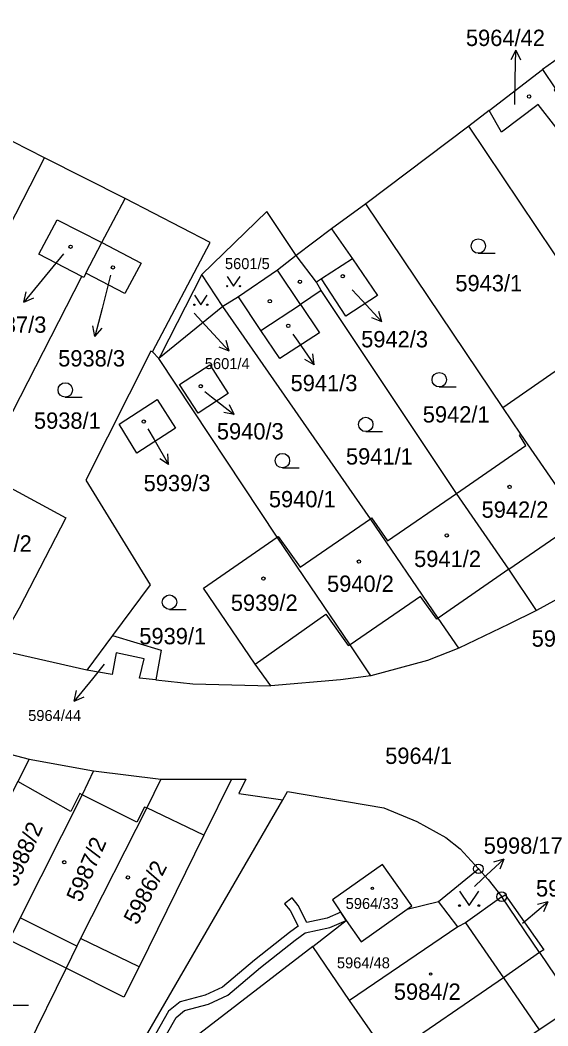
# Model space of a CAD drawing. Extents: x -644096 to -634268, y -1141430 to -1133463.
# Drawn here: x -639627.9 to -639573, y -1138928.4 to -1138823.8 of the extents above; entities that cross this region are included whole.
import ezdxf

# ---------------------------------------------------------------- set-up
doc = ezdxf.new("R2010")
doc.units = 0
for name, color, linetype in [('_CIVIL_CONSTRUCTION', 7, 'Continuous'), ('B_Hranice _3D', 7, 'Continuous'), ('M_Svah_Nasyp', 7, 'Continuous'), ('M_Svah_Zarez', 7, 'Continuous'), ('svrsek_osa_sjezdy', 7, 'Continuous'), ('svrsek_osa_terminal_VRT', 7, 'Continuous'), ('svrsek_osa_VRT', 7, 'Continuous'), ('svrsek_popisy_VRT', 7, 'Continuous'), ('terminal_VRT', 7, 'Continuous')]:
    doc.layers.add(name, color=color, linetype=linetype)

msp = doc.modelspace()

# ---------------------------------------------------------------- linework, layer by layer
at = {"layer": '_CIVIL_CONSTRUCTION'}
for centre, radius in [((-639580.24, -1138912.09), 0.5), ((-639580.24, -1138912.09), 0.0303), ((-639577.82, -1138914.99), 0.5), ((-639577.82, -1138914.99), 0.0303)]:
    msp.add_circle(centre, radius, dxfattribs=at)
at = {"layer": 'B_Hranice _3D'}
msp.add_lwpolyline([(-639615.83, -1138934.86), (-639611.7, -1138927.57), (-639610.82, -1138926.84), (-639608.33, -1138926.18), (-639606.31, -1138925.25), (-639602.91, -1138922.37), (-639599.29, -1138919.5), (-639598.25, -1138918.74), (-639595.69, -1138918.18), (-639593.99, -1138917.46), (-639594.56, -1138916.61), (-639595.99, -1138917.22), (-639598.08, -1138917.67), (-639599, -1138915.89), (-639599.63, -1138915.1), (-639600.41, -1138915.72), (-639599.84, -1138916.43), (-639599, -1138918.05), (-639599.89, -1138918.7), (-639603.55, -1138921.59), (-639606.85, -1138924.39), (-639608.67, -1138925.24), (-639611.28, -1138925.92), (-639612.48, -1138926.91), (-639616.67, -1138934.32)], dxfattribs=at)
at = {"layer": 'M_Svah_Nasyp'}
for p, q in [((-639593.35, -1138848.64), (-639596.58, -1138850.72)), ((-639598.76, -1138853.37), (-639601.15, -1138849.8)), ((-639602.87, -1138856.07), (-639598.76, -1138853.37)), ((-639577.07, -1138880.92), (-639569.66, -1138875.81)), ((-639577.07, -1138880.92), (-639584.44, -1138886.03)), ((-639586.25, -1138883.75), (-639593.6, -1138888.77)), ((-639584.57, -1138886.11), (-639586.25, -1138883.75)), ((-639603.47, -1138890.8), (-639596.13, -1138885.58)), ((-639596.13, -1138885.58), (-639593.8, -1138888.87)), ((-639584.44, -1138886.03), (-639584.57, -1138886.11)), ((-639593.8, -1138888.87), (-639593.6, -1138888.77)), ((-639622.65, -1138906.12), (-639628.16, -1138903.02)), ((-639621.71, -1138904.25), (-639622.65, -1138906.12)), ((-639621.45, -1138904.38), (-639621.71, -1138904.25)), ((-639615.79, -1138907.24), (-639621.45, -1138904.38)), ((-639614.99, -1138905.66), (-639615.79, -1138907.24)), ((-639614.73, -1138905.76), (-639614.99, -1138905.66)), ((-639608.8, -1138908.6), (-639614.73, -1138905.76)), ((-639622.01, -1138920.15), (-639627.9, -1138917.2)), ((-639581.59, -1138917.72), (-639577.64, -1138923.43)), ((-639615.55, -1138922.3), (-639621.65, -1138919.34)), ((-639577.64, -1138923.43), (-639573.92, -1138928.85))]:
    msp.add_line(p, q, dxfattribs=at)
at = {"layer": 'M_Svah_Zarez'}
for centre, radius in [((-639574.97, -1138831.74), 0.175), ((-639622.67, -1138847.37), 0.175), ((-639618.26, -1138849.52), 0.175), ((-639594.35, -1138850.44), 0.175), ((-639598.81, -1138851.01), 0.175), ((-639601.94, -1138853.04), 0.175), ((-639600.03, -1138855.6), 0.175), ((-639609.13, -1138861.88), 0.175), ((-639615.06, -1138865.56), 0.175), ((-639577, -1138872.36), 0.175), ((-639583.54, -1138877.4), 0.175), ((-639592.67, -1138880.13), 0.175), ((-639602.61, -1138881.9), 0.175), ((-639623.33, -1138911.4), 0.175), ((-639616.71, -1138912.98), 0.175), ((-639591.27, -1138914.13), 0.117), ((-639585.22, -1138923.04), 0.117)]:
    msp.add_circle(centre, radius, dxfattribs=at)
at = {"layer": 'svrsek_osa_sjezdy'}
for p, q in [((-639580.25, -1138848.05), (-639578.5, -1138848.05)), ((-639584.31, -1138861.96), (-639582.56, -1138861.96)), ((-639623.22, -1138863.02), (-639621.47, -1138863.02)), ((-639591.96, -1138866.61), (-639590.21, -1138866.61)), ((-639600.63, -1138870.37), (-639598.88, -1138870.37)), ((-639612.38, -1138885.1), (-639610.63, -1138885.1)), ((-639628.79, -1138926.27), (-639627.04, -1138926.27))]:
    msp.add_line(p, q, dxfattribs=at)
for points in [[(-639606.38, -1138850.46), (-639605.71, -1138851.47), (-639605.04, -1138850.46)], [(-639609.79, -1138852.4), (-639609.12, -1138853.41), (-639608.45, -1138852.4)], [(-639582.2, -1138914.42), (-639581.2, -1138915.92), (-639580.2, -1138914.42)]]:
    msp.add_lwpolyline(points, dxfattribs=at)
for centre, radius in [((-639580.25, -1138847.3), 0.75), ((-639606.38, -1138851.47), 0.067), ((-639605.04, -1138851.47), 0.067), ((-639609.79, -1138853.41), 0.067), ((-639608.45, -1138853.41), 0.067), ((-639584.31, -1138861.21), 0.75), ((-639623.22, -1138862.27), 0.75), ((-639591.96, -1138865.86), 0.75), ((-639600.63, -1138869.62), 0.75), ((-639612.38, -1138884.35), 0.75), ((-639582.2, -1138915.92), 0.1), ((-639580.2, -1138915.92), 0.1)]:
    msp.add_circle(centre, radius, dxfattribs=at)
at = {"layer": 'svrsek_osa_terminal_VRT'}
msp.add_arc((-642050.26, -1145189.6), 8802.25, 41.413152, 75.317049, dxfattribs=at)
at = {"layer": 'svrsek_popisy_VRT'}
for p, q in [((-639576.36, -1138826.92), (-639576.88, -1138827.91)), ((-639576.41, -1138829.92), (-639576.36, -1138826.92)), ((-639576.36, -1138826.92), (-639575.87, -1138827.93)), ((-639576.46, -1138832.57), (-639576.41, -1138829.92)), ((-639623.42, -1138848.12), (-639625.64, -1138850.82)), ((-639618.51, -1138850.32), (-639619.4, -1138853.79)), ((-639625.64, -1138850.82), (-639627.53, -1138853.15)), ((-639627.53, -1138853.15), (-639627.29, -1138852.06)), ((-639593.39, -1138851.85), (-639592.33, -1138852.98)), ((-639627.53, -1138853.15), (-639626.51, -1138852.69)), ((-639592.33, -1138852.98), (-639590.28, -1138855.18)), ((-639619.4, -1138853.79), (-639620.13, -1138856.7)), ((-639609.81, -1138854.29), (-639608.21, -1138856.02)), ((-639590.28, -1138855.18), (-639590.6, -1138854.1)), ((-639620.13, -1138856.7), (-639620.37, -1138855.61)), ((-639590.28, -1138855.18), (-639591.33, -1138854.78)), ((-639620.13, -1138856.7), (-639619.4, -1138855.85)), ((-639608.21, -1138856.02), (-639606.16, -1138858.22)), ((-639599.55, -1138856.45), (-639599.04, -1138857.18)), ((-639606.16, -1138858.22), (-639606.48, -1138857.14)), ((-639599.04, -1138857.18), (-639597.32, -1138859.64)), ((-639606.16, -1138858.22), (-639607.21, -1138857.82)), ((-639597.32, -1138859.64), (-639597.48, -1138858.53)), ((-639597.32, -1138859.64), (-639598.3, -1138859.1)), ((-639608.7, -1138862.43), (-639608.01, -1138862.97)), ((-639608.01, -1138862.97), (-639605.65, -1138864.82)), ((-639605.65, -1138864.82), (-639606.13, -1138863.81)), ((-639605.65, -1138864.82), (-639606.74, -1138864.6)), ((-639614.63, -1138866.31), (-639613.97, -1138867.44)), ((-639613.97, -1138867.44), (-639612.47, -1138870.04)), ((-639612.47, -1138870.04), (-639612.54, -1138868.92)), ((-639612.47, -1138870.04), (-639613.4, -1138869.42)), ((-639619.19, -1138890.79), (-639620.4, -1138892.31)), ((-639620.4, -1138892.31), (-639622.29, -1138894.64)), ((-639622.29, -1138894.64), (-639622.05, -1138893.55)), ((-639622.29, -1138894.64), (-639621.27, -1138894.18)), ((-639579.8, -1138913.14), (-639577.6, -1138911.09)), ((-639577.6, -1138911.09), (-639578.68, -1138911.41)), ((-639577.6, -1138911.09), (-639578, -1138912.14)), ((-639580.64, -1138913.92), (-639579.8, -1138913.14)), ((-639575.32, -1138917.47), (-639573.02, -1138915.54)), ((-639573.02, -1138915.54), (-639574.11, -1138915.8)), ((-639573.02, -1138915.54), (-639573.47, -1138916.57)), ((-639575.64, -1138917.73), (-639575.32, -1138917.47))]:
    msp.add_line(p, q, dxfattribs=at)
at = {"layer": 'terminal_VRT'}
for p, q in [((-639570.56, -1138826.78), (-639573.56, -1138828.94)), ((-639579.13, -1138833.21), (-639573.56, -1138828.94)), ((-639579.13, -1138833.21), (-639581.25, -1138834.83)), ((-639625.39, -1138838.11), (-639633.48, -1138834.01)), ((-639581.25, -1138834.83), (-639591.97, -1138842.9)), ((-639566.64, -1138856.63), (-639581.25, -1138834.83)), ((-639616.98, -1138842.34), (-639625.39, -1138838.11)), ((-639619.41, -1138846.94), (-639616.98, -1138842.34)), ((-639591.97, -1138842.9), (-639595.51, -1138845.51)), ((-639577.7, -1138864.1), (-639591.97, -1138842.9)), ((-639595.51, -1138845.51), (-639599.19, -1138848.29)), ((-639621.07, -1138850.12), (-639619.41, -1138846.94)), ((-639597.1, -1138851.06), (-639599.19, -1138848.29)), ((-639606.82, -1138853.58), (-639609.03, -1138850.26)), ((-639631.03, -1138869.08), (-639621.49, -1138850.48)), ((-639596.6, -1138851.92), (-639597.1, -1138851.06)), ((-639582.51, -1138873.03), (-639596.6, -1138851.92)), ((-639605.2, -1138852.59), (-639606.82, -1138853.58)), ((-639606.82, -1138853.58), (-639613.49, -1138858.99)), ((-639591.47, -1138875.68), (-639606.82, -1138853.58)), ((-639613.49, -1138858.99), (-639614.13, -1138858.3)), ((-639601.19, -1138877.57), (-639613.49, -1138858.99)), ((-639575.81, -1138866.86), (-639577.7, -1138864.1)), ((-639614.39, -1138882.53), (-639618.31, -1138887.83)), ((-639618.31, -1138887.83), (-639620.98, -1138891.43)), ((-639620.98, -1138891.43), (-639630.49, -1138889.27)), ((-639613.81, -1138892.44), (-639615.5, -1138892.27)), ((-639613.81, -1138892.44), (-639609.94, -1138892.83)), ((-639609.94, -1138892.83), (-639601.82, -1138893.04)), ((-639633.48, -1138898.97), (-639626.99, -1138900.69)), ((-639626.99, -1138900.69), (-639620.3, -1138901.91)), ((-639620.3, -1138901.91), (-639613.28, -1138902.76)), ((-639613.28, -1138902.76), (-639605.93, -1138902.77)), ((-639584.39, -1138915.49), (-639580.24, -1138912.09)), ((-639573.89, -1138920.81), (-639577.82, -1138914.99)), ((-639587.65, -1138916.29), (-639584.39, -1138915.49)), ((-639582.37, -1138918.14), (-639584.39, -1138915.49)), ((-639597.47, -1138920.18), (-639593.99, -1138917.46)), ((-639582.37, -1138918.14), (-639593.65, -1138925.8)), ((-639623.14, -1138922.41), (-639629.08, -1138919.49)), ((-639593.65, -1138925.8), (-639597.47, -1138920.18)), ((-639573.89, -1138920.81), (-639570.15, -1138926.35)), ((-639623.14, -1138922.41), (-639632.35, -1138941.19)), ((-639589.58, -1138931.6), (-639593.65, -1138925.8))]:
    msp.add_line(p, q, dxfattribs=at)
for points in [[(-639573.56, -1138828.94), (-639572.23, -1138830.96), (-639572.36, -1138831.05), (-639570.61, -1138833.71), (-639572.18, -1138834.92), (-639574.04, -1138832.56), (-639577.85, -1138835.44), (-639579.13, -1138833.21)], [(-639638.99, -1138864.85), (-639638.05, -1138862.79), (-639625.39, -1138838.11)], [(-639614.13, -1138858.3), (-639608.15, -1138846.93), (-639616.98, -1138842.34)], [(-639599.19, -1138848.29), (-639602.26, -1138843.71), (-639609.03, -1138850.26)], [(-639621.49, -1138850.48), (-639625.96, -1138848.16), (-639624.05, -1138844.57), (-639619.41, -1138846.94)], [(-639595.51, -1138845.51), (-639593.35, -1138848.64), (-639590.73, -1138852.44), (-639594.02, -1138854.6), (-639596.58, -1138850.72), (-639597.1, -1138851.06)], [(-639619.41, -1138846.94), (-639615.34, -1138849.08), (-639617.02, -1138852.24), (-639621.07, -1138850.12)], [(-639599.19, -1138848.29), (-639601.15, -1138849.8), (-639605.2, -1138852.59)], [(-639621.07, -1138850.12), (-639621.3, -1138850.57), (-639621.49, -1138850.48)], [(-639609.03, -1138850.26), (-639613.3, -1138858.69), (-639613.49, -1138858.99)], [(-639596.6, -1138851.92), (-639598.76, -1138853.37), (-639596.78, -1138856.32), (-639600.9, -1138859.01), (-639602.87, -1138856.07), (-639605.2, -1138852.59)], [(-639614.13, -1138858.3), (-639614.31, -1138858.22), (-639621.09, -1138871.67), (-639614.39, -1138882.53)], [(-639608.17, -1138859.64), (-639606.26, -1138862.63), (-639609.39, -1138864.68), (-639611.33, -1138861.72), (-639608.17, -1138859.64)], [(-639577.7, -1138864.1), (-639570.22, -1138858.89), (-639570.12, -1138859.02)], [(-639613.65, -1138863.28), (-639611.76, -1138866.23), (-639615.78, -1138868.83), (-639617.62, -1138865.84), (-639613.65, -1138863.28)], [(-639582.51, -1138873.03), (-639575.32, -1138868.05), (-639575.97, -1138866.97), (-639575.81, -1138866.86)], [(-639566.35, -1138880.62), (-639569.66, -1138875.81), (-639575.81, -1138866.86)], [(-639631.85, -1138870.88), (-639623.15, -1138875.59), (-639628.03, -1138884.96), (-639630.49, -1138889.27)], [(-639591.47, -1138875.68), (-639591.35, -1138875.59), (-639589.7, -1138877.96), (-639582.51, -1138873.03)], [(-639574.19, -1138885.2), (-639577.07, -1138880.92), (-639582.51, -1138873.03)], [(-639601.19, -1138877.57), (-639601.08, -1138877.51), (-639598.8, -1138880.72), (-639591.47, -1138875.68)], [(-639582.29, -1138889.12), (-639584.44, -1138886.03), (-639591.47, -1138875.68)], [(-639601.82, -1138893.04), (-639603.47, -1138890.8), (-639608.85, -1138882.88), (-639601.19, -1138877.57)], [(-639591.45, -1138892.01), (-639593.6, -1138888.77), (-639601.19, -1138877.57)], [(-639566.35, -1138880.62), (-639568.81, -1138882.26), (-639574.19, -1138885.2)], [(-639574.19, -1138885.2), (-639577.08, -1138886.63), (-639582.29, -1138889.12)], [(-639618.31, -1138887.83), (-639613.24, -1138889.33), (-639613.81, -1138892.44)], [(-639615.5, -1138892.27), (-639615, -1138890.26), (-639617.92, -1138889.63), (-639618.36, -1138891.88), (-639620.98, -1138891.43)], [(-639582.29, -1138889.12), (-639585.54, -1138890.43), (-639591.45, -1138892.01)], [(-639591.45, -1138892.01), (-639594.6, -1138892.42), (-639601.82, -1138893.04)], [(-639626.99, -1138900.69), (-639628.16, -1138903.02), (-639635.28, -1138916.96)], [(-639620.3, -1138901.91), (-639621.45, -1138904.38), (-639627.9, -1138917.2), (-639628.47, -1138918.34), (-639629.08, -1138919.49)], [(-639613.28, -1138902.76), (-639614.73, -1138905.76), (-639621.65, -1138919.34), (-639622.01, -1138920.15), (-639623.14, -1138922.41)], [(-639605.93, -1138902.77), (-639608.8, -1138908.6), (-639615.55, -1138922.3), (-639617.12, -1138925.45), (-639623.14, -1138922.41)], [(-639605.93, -1138902.77), (-639604.42, -1138902.77), (-639605.15, -1138904.24), (-639600.59, -1138904.9)], [(-639600.59, -1138904.9), (-639600.1, -1138904.04), (-639590.07, -1138905.76), (-639586.66, -1138907.16), (-639583.63, -1138908.84), (-639582.15, -1138910.01), (-639580.24, -1138912.09)], [(-639636.31, -1138949.04), (-639626.14, -1138949.01), (-639600.59, -1138904.9)], [(-639587.65, -1138916.29), (-639587.17, -1138915.95), (-639590.22, -1138911.65), (-639595.42, -1138915.31), (-639593.99, -1138917.46)], [(-639580.24, -1138912.09), (-639579.21, -1138913.21), (-639577.82, -1138914.99)], [(-639577.82, -1138914.99), (-639581.59, -1138917.72), (-639582.37, -1138918.14)], [(-639577.82, -1138914.99), (-639577.45, -1138914.79), (-639573.45, -1138920.51), (-639573.89, -1138920.81)], [(-639593.99, -1138917.46), (-639592.43, -1138919.68), (-639587.65, -1138916.29)], [(-639597.47, -1138920.18), (-639613.13, -1138932.23), (-639622.89, -1138948.28)], [(-639573.89, -1138920.81), (-639577.64, -1138923.43), (-639589.46, -1138931.55), (-639589.58, -1138931.6)], [(-639570.15, -1138926.35), (-639573.92, -1138928.85), (-639586.33, -1138937.4), (-639587.13, -1138937.92), (-639587.79, -1138938.35)]]:
    msp.add_lwpolyline(points, dxfattribs=at)

# ---------------------------------------------------------------- texts
at = {"layer": 'svrsek_osa_VRT'}
for s, height, p in [('5964/42', 1.7, (-639581.54, -1138826.49)), ('5601/5', 1.14, (-639606.61, -1138849.7)), ('5943/1', 1.7, (-639582.64, -1138852.01)), ('5937/3', 1.7, (-639632.14, -1138856.32)), ('5942/3', 1.7, (-639592.44, -1138857.84)), ('5938/3', 1.7, (-639623.96, -1138859.83)), ('5601/4', 1.14, (-639608.7, -1138860.1)), ('5941/3', 1.7, (-639599.78, -1138862.4)), ('5942/1', 1.7, (-639586.03, -1138865.66)), ('5938/1', 1.7, (-639626.48, -1138866.31)), ('5940/3', 1.7, (-639607.45, -1138867.42)), ('5941/1', 1.7, (-639594.02, -1138870.03)), ('5939/3', 1.7, (-639615.07, -1138872.81)), ('5940/1', 1.7, (-639602.04, -1138874.48)), ('5942/2', 1.7, (-639579.91, -1138875.57)), ('5938/2', 1.7, (-639633.66, -1138879.09)), ('5941/2', 1.7, (-639586.93, -1138880.69)), ('5940/2', 1.7, (-639595.99, -1138883.28)), ('5939/2', 1.7, (-639606, -1138885.26)), ('5939/1', 1.7, (-639615.52, -1138888.73)), ('5964/50', 1.7, (-639574.7, -1138888.98)), ('5964/44', 1.14, (-639627.08, -1138896.71)), ('5964/1', 1.7, (-639589.94, -1138901.18)), ('5998/17', 1.7, (-639579.69, -1138910.52)), ('5984/3', 1.7, (-639574.25, -1138914.97)), ('5964/33', 1.14, (-639594.05, -1138916.27)), ('5964/48', 1.14, (-639594.96, -1138922.44)), ('5984/2', 1.7, (-639589.04, -1138925.72))]:
    msp.add_text(s, height=height, dxfattribs=at).set_placement(p)
for s, rotation, p in [('5988/2', 66, (-639628.33, -1138914.06)), ('5987/2', 67, (-639621.61, -1138915.67)), ('5986/2', 63, (-639615.73, -1138918.02))]:
    msp.add_text(s, height=1.7, rotation=rotation, dxfattribs=at).set_placement(p)

doc.saveas('drawing.dxf')
